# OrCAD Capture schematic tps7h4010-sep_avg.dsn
size A; title: TPS7H4010-SEP Radiation Tolerant 3.5-V to 32-V, 6-A; rev: A; note: Datasheet: SNVSBL0A    EVM: SNVU744; note: Synchronous Step-Down Converter in Space Enhanced Plastic
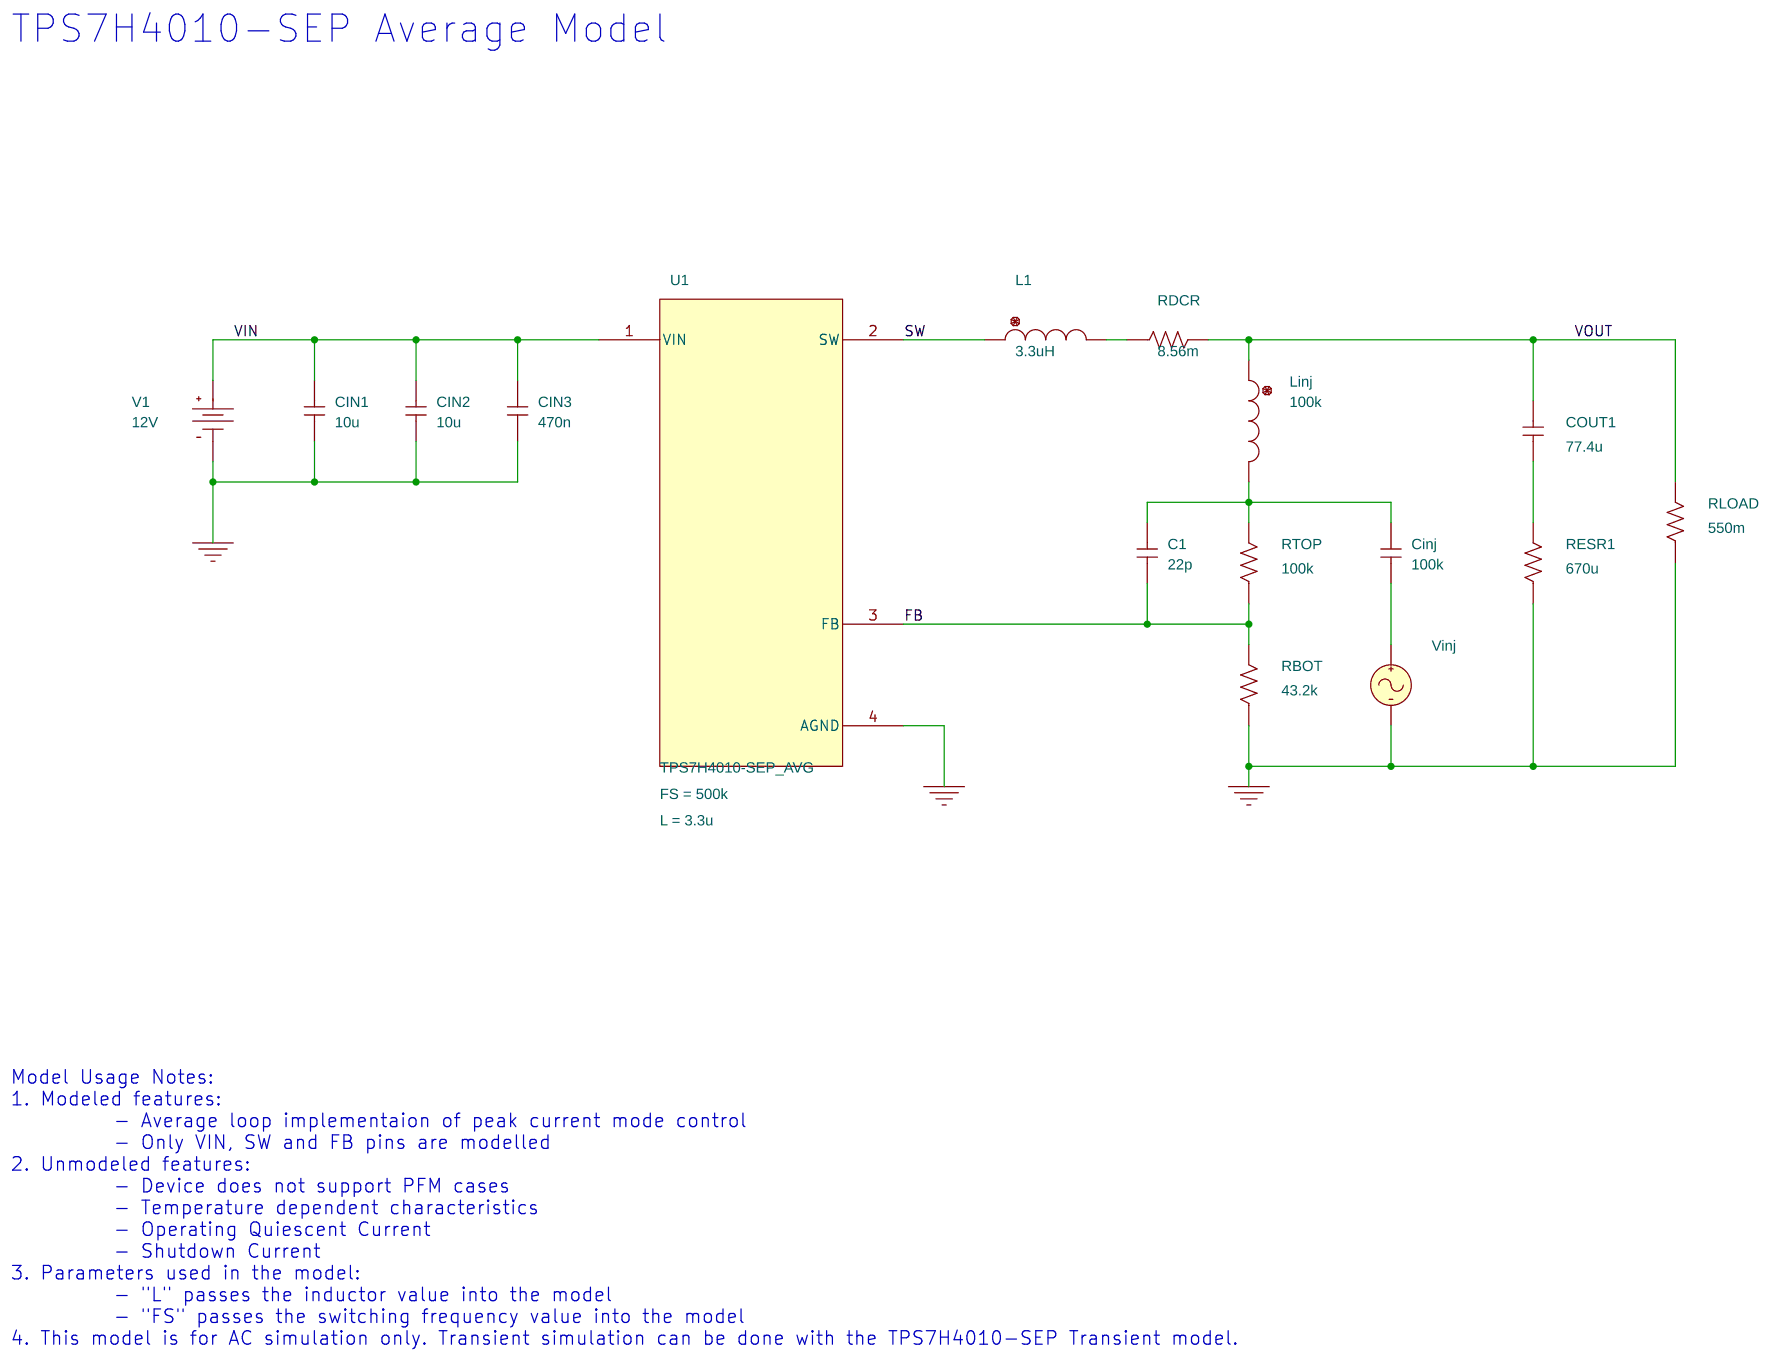
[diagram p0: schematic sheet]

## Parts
C1  22p  [cap196]
CIN1  10u  [cap196]
CIN2  10u  [cap196]
CIN3  470n  [cap196]
Cinj  100k  [cap196]
COUT1  77.4u  [cap196]
L1  3.3uH  [DISC350x175LS200x100034]
Linj  100k  [DISC350x175LS200x100034]
RBOT  43.2k  [AXRC05]
RDCR  8.56m  [AXRC05]
RESR1  670u  [AXRC05]
RLOAD  550m  [AXRC05]
RTOP  100k  [AXRC05]
U1  TPS7H4010-SEP_AVG
V1  VDC
Vinj  VAC

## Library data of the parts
C1 CIN1-CIN3 Cinj COUT1 = C
L1 Linj = L
RBOT RDCR RESR1 RLOAD RTOP = R
U1 = TPS7H4010-SEP_AVG_1: FS: 500k; L: 3.3u
V1 = VDC: DC: 12V
Vinj = VAC

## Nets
VIN: CIN1.2 CIN2.2 CIN3.2 U1.1(VIN) V1.0(+)
0: CIN1.1 CIN2.1 CIN3.1 RBOT.1 RESR1.1 RLOAD.1 U1.4(AGND) V1.1(-) Vinj.2(-)
FB: C1.1 RBOT.2 RTOP.1 U1.3(FB)
SW: L1.1 U1.2(SW)
VOUT: COUT1.2 Linj.1 RDCR.2 RLOAD.2
N01347: L1.2 RDCR.1
N01458: C1.2 Cinj.2 Linj.2 RTOP.2
N01799: Cinj.1 Vinj.1(+)
N01823: COUT1.1 RESR1.2

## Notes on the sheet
- TPS7H4010-SEP Average Model
- Model Usage Notes:
  1. Modeled features:
            - Average loop implementaion of peak current mode control
            - Only VIN, SW and FB pins are modelled
  2. Unmodeled features:
            - Device does not support PFM cases
            - Temperature dependent characteristics
            - Operating Quiescent Current
            - Shutdown Current
  3. Parameters used in the model:
            - "L" passes the inductor value into the model
            - "FS" passes the switching frequency value into the model
  4. This model is for AC simulation only. Transient simulation can be done with the TPS7H4010-SEP Transient model.
